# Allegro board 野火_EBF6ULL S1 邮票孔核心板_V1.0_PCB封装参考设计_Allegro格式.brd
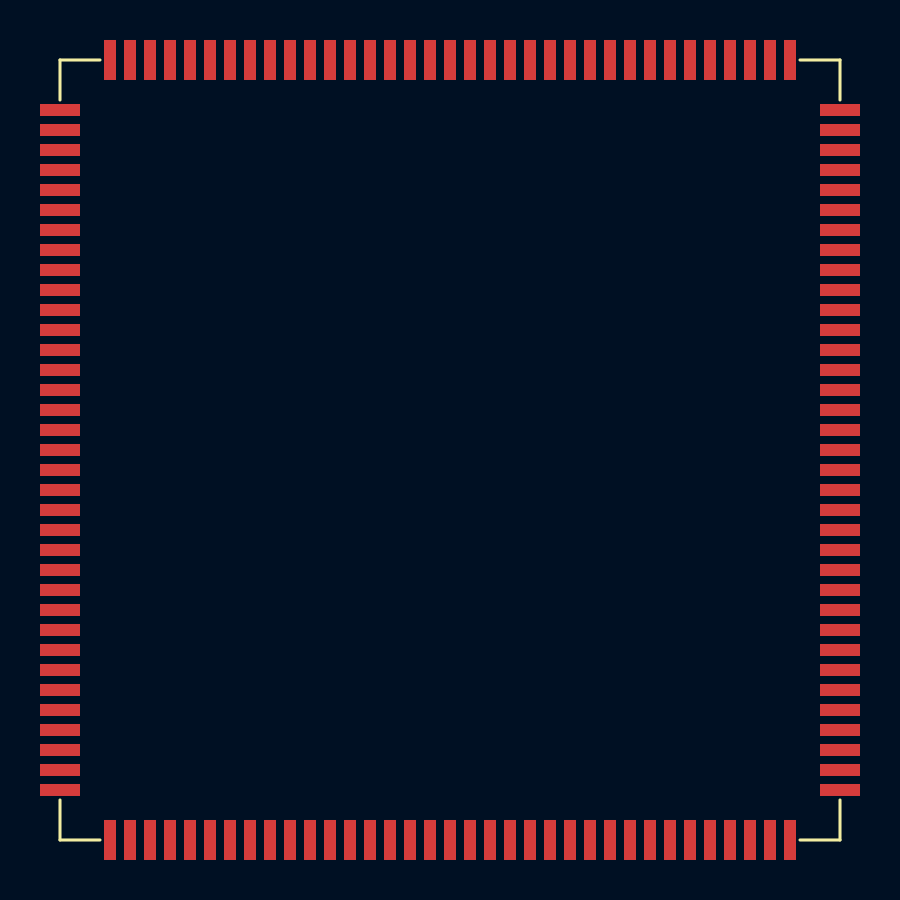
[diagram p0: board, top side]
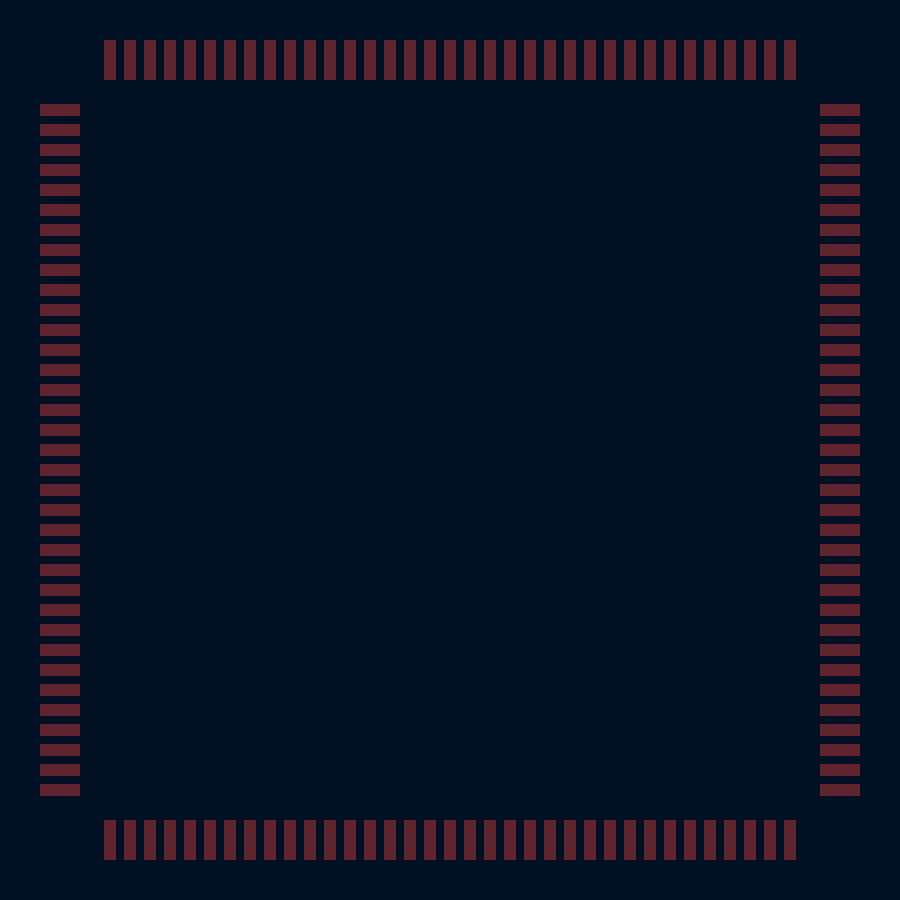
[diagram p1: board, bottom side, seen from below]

No outline. copper layers: TOP, BOTTOM. Coordinates in mm from the lowest, leftmost part position.

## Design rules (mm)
net group DIFFPAIR0: nets DM3 DP3
net group DIFFPAIR1: nets DM4 DP4
net group DIFFPAIR2: nets DM1 DP1
net group DIFFPAIR3: nets DM2 DP2
net group DIFFPAIR4: nets N50301 N50345
net group ETH1_RX: nets ETH1_RXM ETH1_RXP
net group ETH1_TX: nets ETH1_TXM ETH1_TXP
net group HDMI_TX0: nets HDMI_TX0_N HDMI_TX0_P
net group HDMI_TX1: nets HDMI_TX1_N HDMI_TX1_P
net group HDMI_TX2: nets HDMI_TX2_N HDMI_TX2_P
net group HDMI_TXC: nets HDMI_TXC_N HDMI_TXC_P
net group J3: nets N17041284 N17041286
net group J4: nets N17061904 N17061906
net group LVDS_CLK: nets LVDS_CLKN LVDS_CLKP
net group LVDS_TX0: nets LVDS_TX0N LVDS_TX0P
net group LVDS_TX1: nets LVDS_TX1N LVDS_TX1P
net group LVDS_TX2: nets LVDS_TX2N LVDS_TX2P
net group LVDS_TX3: nets LVDS_TX3N LVDS_TX3P
net group PHY-RX: nets ETH2_RXM ETH2_RXP
net group PHY-TX: nets ETH2_TXM ETH2_TXP
net group USB_OTG: nets USB_OTG2_DN USB_OTG2_DP
net group USB_OTG1: nets USB_OTG1_DN USB_OTG1_DP
net group PWR: nets 3V3 3V3_IN 3V3_WIFI 5V 5V_IN 5V_USB 12V 12V_IN GND HUB_1V8 HUB_3V3 VCC_PANEL

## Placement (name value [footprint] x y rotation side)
J12  iMX6ULL_SOM_S1  [IMX6ULL_SOM_S1_140P_39X39]  0 0 90 top

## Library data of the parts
J12 = iMX6ULL_SOM_S1_1

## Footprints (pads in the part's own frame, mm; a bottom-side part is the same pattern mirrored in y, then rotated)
IMX6ULL_SOM_S1_140P_39X39
  rect 0.6x2 smd: 1(17,19.5) 2(16,19.5) 3(15,19.5) 4(14,19.5) 5(13,19.5) 6(12,19.5) 7(11,19.5) 8(10,19.5) 9(9,19.5) 10(8,19.5) 11(7,19.5) 12(6,19.5) 13(5,19.5) 14(4,19.5) 15(3,19.5) 16(2,19.5) 17(1,19.5) 18(0,19.5) 19(-1,19.5) 20(-2,19.5) 21(-3,19.5) 22(-4,19.5) 23(-5,19.5) 24(-6,19.5) 25(-7,19.5) 26(-8,19.5) 27(-9,19.5) 28(-10,19.5) 29(-11,19.5) 30(-12,19.5) 31(-13,19.5) 32(-14,19.5) 33(-15,19.5) 34(-16,19.5) 35(-17,19.5) 71(-17,-19.5) 72(-16,-19.5) 73(-15,-19.5) 74(-14,-19.5) 75(-13,-19.5) 76(-12,-19.5) 77(-11,-19.5) 78(-10,-19.5) 79(-9,-19.5) 80(-8,-19.5) 81(-7,-19.5) 82(-6,-19.5) 83(-5,-19.5) 84(-4,-19.5) 85(-3,-19.5) 86(-2,-19.5) 87(-1,-19.5) 88(0,-19.5) 89(1,-19.5) 90(2,-19.5) 91(3,-19.5) 92(4,-19.5) 93(5,-19.5) 94(6,-19.5) 95(7,-19.5) 96(8,-19.5) 97(9,-19.5) 98(10,-19.5) 99(11,-19.5) 100(12,-19.5) 101(13,-19.5) 102(14,-19.5) 103(15,-19.5) 104(16,-19.5) 105(17,-19.5)
  rect 2x0.6 smd: 36(-19.5,17) 37(-19.5,16) 38(-19.5,15) 39(-19.5,14) 40(-19.5,13) 41(-19.5,12) 42(-19.5,11) 43(-19.5,10) 44(-19.5,9) 45(-19.5,8) 46(-19.5,7) 47(-19.5,6) 48(-19.5,5) 49(-19.5,4) 50(-19.5,3) 51(-19.5,2) 52(-19.5,1) 53(-19.5,0) 54(-19.5,-1) 55(-19.5,-2) 56(-19.5,-3) 57(-19.5,-4) 58(-19.5,-5) 59(-19.5,-6) 60(-19.5,-7) 61(-19.5,-8) 62(-19.5,-9) 63(-19.5,-10) 64(-19.5,-11) 65(-19.5,-12) 66(-19.5,-13) 67(-19.5,-14) 68(-19.5,-15) 69(-19.5,-16) 70(-19.5,-17) 106(19.5,-17) 107(19.5,-16) 108(19.5,-15) 109(19.5,-14) 110(19.5,-13) 111(19.5,-12) 112(19.5,-11) 113(19.5,-10) 114(19.5,-9) 115(19.5,-8) 116(19.5,-7) 117(19.5,-6) 118(19.5,-5) 119(19.5,-4) 120(19.5,-3) 121(19.5,-2) 122(19.5,-1) 123(19.5,0) 124(19.5,1) 125(19.5,2) 126(19.5,3) 127(19.5,4) 128(19.5,5) 129(19.5,6) 130(19.5,7) 131(19.5,8) 132(19.5,9) 133(19.5,10) 134(19.5,11) 135(19.5,12) 136(19.5,13) 137(19.5,14) 138(19.5,15) 139(19.5,16) 140(19.5,17)

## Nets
3V3_IN: J12.138 J12.139 J12.140
5V: J12.89
GND: J12.9 J12.18 J12.27 J12.33 J12.40 J12.53 J12.64 J12.70 J12.77 J12.88 J12.92 J12.96 J12.115 J12.124 J12.133 J12.134 J12.135
VDD_COIN_3V: J12.137
BOOT_MODE0: J12.66
BOOT_MODE1: J12.65
CLK1_N: J12.97
CLK1_P: J12.98
CSI_DATA0: J12.41
CSI_DATA1: J12.42
CSI_DATA2: J12.43
CSI_DATA3: J12.44
CSI_DATA4: J12.45
CSI_DATA5: J12.46
CSI_DATA6: J12.47
CSI_DATA7: J12.48
CSI_HSYNC: J12.49
CSI_MCLK: J12.52
CSI_PIXCLK: J12.51
CSI_VSYNC: J12.50
ENET1_CRS_DV: J12.116
ENET1_RXD0: J12.119
ENET1_RXD1: J12.118
ENET1_RXER: J12.117
ENET1_TX_CLK: J12.120
ENET1_TXD0: J12.123
ENET1_TXD1: J12.122
ENET1_TXEN: J12.121
ENET2_CRS_DV: J12.125
ENET2_RXD0: J12.128
ENET2_RXD1: J12.127
ENET2_RXER: J12.126
ENET2_TX_CLK: J12.129
ENET2_TXD0: J12.132
ENET2_TXD1: J12.131
ENET2_TXEN: J12.130
GPIO_0: J12.87
GPIO_1: J12.86
GPIO_2: J12.85
GPIO_3: J12.84
GPIO_4: J12.83
GPIO_5: J12.82
GPIO_6: J12.81
GPIO_7: J12.80
GPIO_8: J12.79
GPIO_9: J12.78
LCD_DATA0: J12.26
LCD_DATA1: J12.25
LCD_DATA2: J12.24
LCD_DATA3: J12.23
LCD_DATA4: J12.22
LCD_DATA5: J12.21
LCD_DATA6: J12.20
LCD_DATA7: J12.19
LCD_DATA8: J12.17
LCD_DATA9: J12.16
LCD_DATA10: J12.15
LCD_DATA11: J12.14
LCD_DATA12: J12.13
LCD_DATA13: J12.12
LCD_DATA14: J12.11
LCD_DATA15: J12.10
LCD_DATA16: J12.8
LCD_DATA17: J12.7
LCD_DATA18: J12.6
LCD_DATA19: J12.5
LCD_DATA20: J12.4
LCD_DATA21: J12.3
LCD_DATA22: J12.2
LCD_DATA23: J12.1
LCD_DE: J12.30
LCD_HSYNC: J12.28
LCD_PCLK: J12.31
LCD_RST: J12.32
LCD_VSYNC: J12.29
ONOFF: J12.69
PMIC_ON_REQ: J12.136
PMIC_STBY_REQ: J12.67
POR_B: J12.68
SAI2_BCLK: J12.73
SAI2_MCLK: J12.76
SAI2_RXD: J12.75
SAI2_SYNC: J12.74
SAI2_TXD: J12.71
SD1_CLK: J12.39
SD1_CMD: J12.38
SD1_DATA0: J12.34
SD1_DATA1: J12.35
SD1_DATA2: J12.36
SD1_DATA3: J12.37
SNVS_TAMPER0: J12.63
SNVS_TAMPER1: J12.62
SNVS_TAMPER2: J12.61
SNVS_TAMPER3: J12.60
SNVS_TAMPER4: J12.59
SNVS_TAMPER5: J12.58
SNVS_TAMPER6: J12.57
SNVS_TAMPER7: J12.56
SNVS_TAMPER8: J12.55
SNVS_TAMPER9: J12.54
SPDIF_TX: J12.72
UART1_CTS: J12.101
UART1_RTS: J12.102
UART1_RXD: J12.99
UART1_TXD: J12.100
UART2_CTS: J12.105
UART2_RTS: J12.106
UART2_RXD: J12.103
UART2_TXD: J12.104
UART3_CTS: J12.109
UART3_RTS: J12.110
UART3_RXD: J12.107
UART3_TXD: J12.108
UART4_RXD: J12.111
UART4_TXD: J12.112
UART5_RXD: J12.113
UART5_TXD: J12.114
USB_OTG1_DN: J12.94
USB_OTG1_DP: J12.95
USB_OTG1_VBUS: J12.93
USB_OTG2_DN: J12.90
USB_OTG2_DP: J12.91
